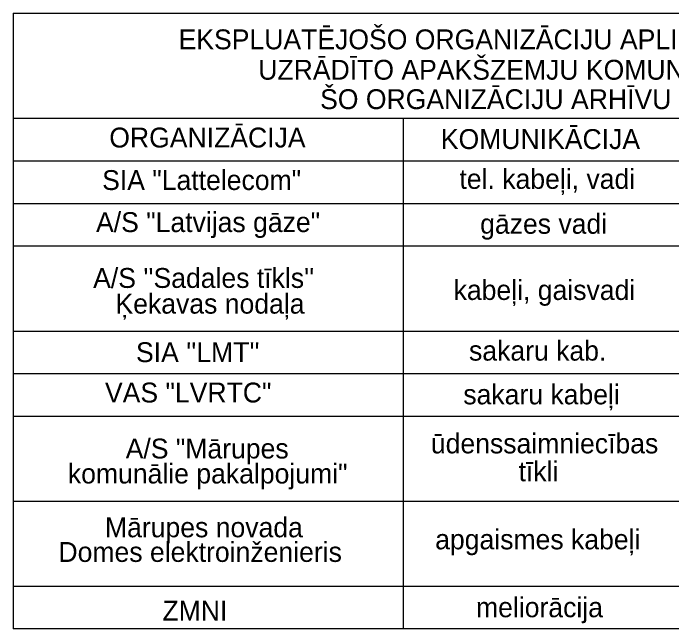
# Model space of a CAD drawing. Extents: x 496127 to 496334, y 303823 to 303967.
# Drawn here: x 496270.36 to 496303.52, y 303848.66 to 303879.64 of the extents above; entities that cross this region are included whole.
import ezdxf

# ---------------------------------------------------------------- set-up
doc = ezdxf.new("R2010")
doc.units = 0
doc.layers.add('RAMI_PLAN_####_TKST_#', color=7, linetype='Continuous')

msp = doc.modelspace()

# ---------------------------------------------------------------- linework, layer by layer
at = {"layer": 'RAMI_PLAN_####_TKST_#'}
for p, q in [((496270.361, 303879.638), (496331.919, 303879.638)), ((496270.361, 303879.638), (496270.361, 303848.658)), ((496331.919, 303874.337), (496270.361, 303874.337)), ((496289.999, 303874.337), (496289.999, 303848.658)), ((496331.919, 303872.195), (496270.361, 303872.195)), ((496331.919, 303870.052), (496270.361, 303870.052)), ((496331.919, 303867.91), (496270.361, 303867.91)), ((496331.919, 303863.626), (496270.361, 303863.626)), ((496331.919, 303861.484), (496270.361, 303861.484)), ((496331.919, 303859.344), (496270.361, 303859.344)), ((496331.919, 303855.064), (496270.361, 303855.064)), ((496331.919, 303850.784), (496270.361, 303850.784)), ((496331.919, 303848.658), (496270.361, 303848.658))]:
    msp.add_line(p, q, dxfattribs=at)

# ---------------------------------------------------------------- texts
for s, p in [(' EKSPLUATĒJOŠO ORGANIZĀCIJU APLIECINĀJUMS PAR PLĀNĀ', (496278.317, 303877.82)), (' UZRĀDĪTO APAKŠZEMJU KOMUNIKĀCIJU ATBILSTĪBU', (496282.327, 303876.29)), (' ŠO ORGANIZĀCIJU ARHĪVU MATERIĀLIEM', (496285.441, 303874.811)), ('ORGANIZĀCIJA', (496275.2, 303872.879)), ('KOMUNIKĀCIJA', (496291.89, 303872.802)), ('SIA "Lattelecom"', (496274.839, 303870.74)), ('tel. kabeļi, vadi', (496292.828, 303870.798)), ('A/S "Latvijas gāze"', (496274.532, 303868.623)), ('gāzes vadi', (496293.87, 303868.538)), ("A/S ''Sadales tīkls'' ", (496274.387, 303865.813)), ('kabeļi, gaisvadi', (496292.534, 303865.207)), ('Ķekavas nodaļa', (496275.512, 303864.519)), ("SIA ''LMT''", (496276.544, 303862.078)), ('sakaru kab.', (496293.31, 303862.155))]:
    msp.add_text(s, height=1, dxfattribs=at).set_placement(p)
for s, p in [('VAS "LVRTC"', (496274.982, 303860.048)), ('sakaru kabeļi', (496293.022, 303859.954)), ('A/S "Mārupes', (496276.025, 303857.23)), ('ūdenssaimniecības', (496291.389, 303857.486)), ('komunālie pakalpojumi"', (496273.115, 303855.971)), ('tīkli', (496295.804, 303856.081)), ('Mārupes novada', (496274.983, 303853.265)), ('apgaismes kabeļi', (496291.606, 303852.658)), ('Domes elektroinženieris', (496272.64, 303852.025)), ('ZMNI', (496277.875, 303849.068)), ('meliorācija', (496293.661, 303849.241))]:
    msp.add_text(s, height=1, rotation=359.9987, dxfattribs=at).set_placement(p)

doc.saveas('drawing.dxf')
